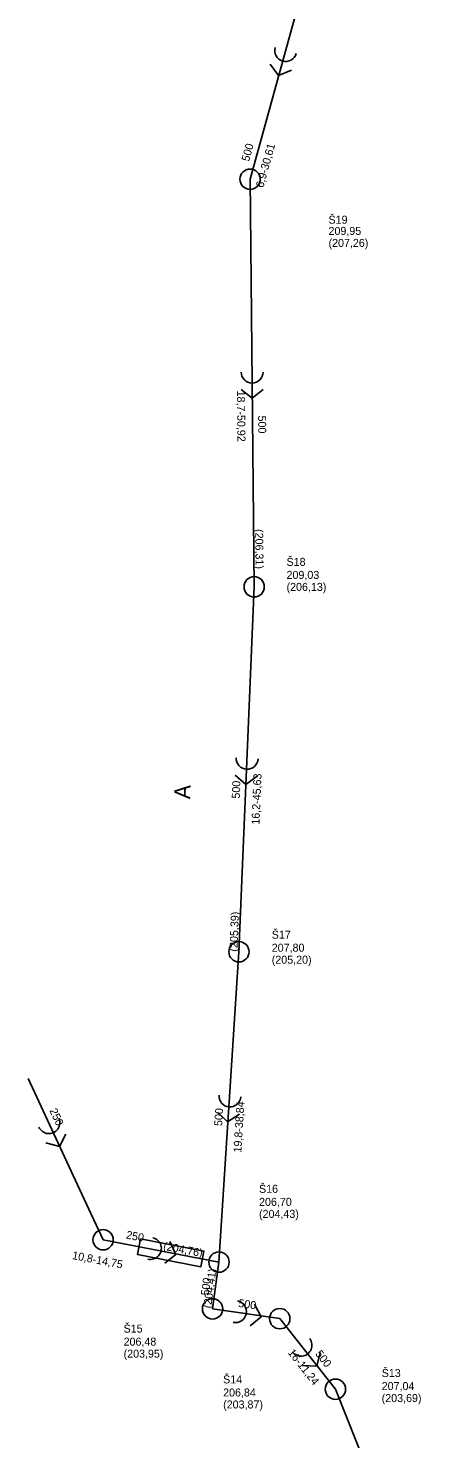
# Model space of a CAD drawing. Extents: x -569540 to -569072, y -1179643 to -1178245.
# Drawn here: x -569540.5 to -569488.5, y -1179470.9 to -1179294.7 of the extents above; entities that cross this region are included whole.
import ezdxf

# ---------------------------------------------------------------- set-up
doc = ezdxf.new("R2010")
doc.units = 0
for name, color, linetype in [('Vrstva 1', 7, 'Continuous'), ('Vrstva 15', 7, 'Continuous'), ('Vrstva 27', 7, 'Continuous'), ('Vrstva 29', 7, 'Continuous'), ('Vrstva 35', 7, 'Continuous'), ('Vrstva 41', 7, 'Continuous'), ('Vrstva 44', 7, 'Continuous'), ('Vrstva 45', 7, 'Continuous'), ('Vrstva 56', 7, 'Continuous'), ('Vrstva 57', 7, 'Continuous')]:
    doc.layers.add(name, color=color, linetype=linetype)

# ---------------------------------------------------------------- blocks, each defined once
blk = doc.blocks.new('100')
at = {"layer": 'Vrstva 1'}
blk.add_circle((0, 0), 1.27, dxfattribs=at)
blk = doc.blocks.new('86')
at = {"layer": 'Vrstva 1'}
blk.add_lwpolyline([(0.79, 1.37), (1.89, 0), (0.79, -1.38)], dxfattribs=at)
blk.add_arc((-1.37, 0), 1.37, 270, 90, dxfattribs=at)

msp = doc.modelspace()

# ---------------------------------------------------------------- linework, layer by layer
at = {"layer": 'Vrstva 15'}
for p, q in [((-569504.59, -1179284.05), (-569512.73, -1179313.56)), ((-569512.73, -1179313.56), (-569512.22, -1179364.48)), ((-569512.22, -1179364.48), (-569514.12, -1179410.07)), ((-569514.12, -1179410.07), (-569516.62, -1179448.83)), ((-569531.11, -1179446.05), (-569516.62, -1179448.83)), ((-569516.62, -1179448.83), (-569517.42, -1179454.68)), ((-569517.42, -1179454.68), (-569509.02, -1179455.9)), ((-569509.02, -1179455.9), (-569502.06, -1179464.71)), ((-569502.06, -1179464.71), (-569488.5, -1179498.74))]:
    msp.add_line(p, q, dxfattribs=at)
msp.add_lwpolyline([(-569540.48, -1179425.88), (-569533.76, -1179440.34), (-569531.11, -1179446.05)], dxfattribs=at)
at = {"layer": 'Vrstva 27'}
msp.add_lwpolyline([(-569526.42, -1179445.93), (-569518.5, -1179447.45), (-569518.88, -1179449.41), (-569526.79, -1179447.9), (-569526.42, -1179445.93)], dxfattribs=at)

# ---------------------------------------------------------------- block references
at = {"layer": 'Vrstva 29'}
for p, xscale, yscale, rotation in [((-569512.73, -1179313.56), 1.000191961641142, 1.000191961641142, 82.91099886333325), ((-569512.22, -1179364.48), 0.9999999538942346, 0.9999999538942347, -92.0000000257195), ((-569514.12, -1179410.07), 0.9999999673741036, 0.9999999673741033, -93.99999995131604), ((-569531.11, -1179446.05), 0.9999999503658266, 0.9999999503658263, 142.00000018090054), ((-569516.62, -1179448.83), 1.000191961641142, 1.000191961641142, -97.08900113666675), ((-569517.42, -1179454.68), 0.9999999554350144, 0.9999999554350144, 126.99999920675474), ((-569509.02, -1179455.9), 0.9999999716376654, 0.9999999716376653, 150.00000103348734), ((-569502.06, -1179464.71), 0.9999999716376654, 0.9999999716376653, 119.99999896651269)]:
    msp.add_blockref('100', p, dxfattribs=dict(at, xscale=xscale, yscale=yscale, rotation=rotation))
at = {"layer": 'Vrstva 41'}
for p, xscale, yscale, rotation in [((-569508.66, -1179298.8), 0.9999999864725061, 0.9999999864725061, -105.99999860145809), ((-569513.17, -1179387.27), 0.9999999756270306, 0.9999999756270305, -93.00000001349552), ((-569515.37, -1179429.45), 0.9999999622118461, 0.999999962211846, -94.99999985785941), ((-569537.33, -1179432.67), 0.9999999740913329, 0.9999999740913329, -65.99999939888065), ((-569523.86, -1179447.44), 1.0045862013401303, 1.00458620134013, -13.17409066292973), ((-569513.22, -1179455.29), 1.00837761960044, 1.00837761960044, -11.626378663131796), ((-569505.54, -1179460.31), 0.9999999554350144, 0.9999999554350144, -53.00000079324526)]:
    msp.add_blockref('86', p, dxfattribs=dict(at, xscale=xscale, yscale=yscale, rotation=rotation))
at = {"layer": 'Vrstva 41', "rotation": -90}
msp.add_blockref('86', (-569512.48, -1179339.02), dxfattribs=at)

# ---------------------------------------------------------------- texts
at = {"layer": 'Vrstva 35'}
msp.add_text('A', height=2, rotation=87.61, dxfattribs=at).set_placement((-569520.23, -1179391.03))
at = {"layer": 'Vrstva 44'}
for s, rotation, p in [('500', 74.57, (-569512.86, -1179311.41)), ('500', 270.57, (-569511.73, -1179343.09)), ('500', 87.61, (-569514.03, -1179390.95)), ('250', 294.92, (-569537.85, -1179429.89)), ('500', 86.32, (-569516.23, -1179431.86)), ('250', 349.15, (-569528.3, -1179445.88)), ('500', 82.25, (-569517.91, -1179453.07)), ('500', 351.7, (-569514.25, -1179454.43)), ('500', 308.34, (-569504.63, -1179460.33))]:
    msp.add_text(s, height=1, rotation=rotation, dxfattribs=at).set_placement(p)
at = {"layer": 'Vrstva 45'}
for s, rotation, p in [('6,9-30,61', 74.57, (-569511.08, -1179314.7)), ('18,7-50,92', 270.57, (-569514.37, -1179339.97)), ('(206,31)', 270.57, (-569512.09, -1179357.27)), ('16,2-45,63', 87.61, (-569511.56, -1179394.21)), ('(205,39)', 87.61, (-569514.32, -1179410.06)), ('19,8-38,84', 86.32, (-569513.83, -1179435.17)), ('(204,76)', 349.15, (-569523.65, -1179447.28)), ('10,8-14,75', 349.15, (-569535.04, -1179448.44)), ('(204,41)', 82.25, (-569517.61, -1179454.65)), ('16-11,24', 308.34, (-569508.06, -1179460.17))]:
    msp.add_text(s, height=1, rotation=rotation, dxfattribs=at).set_placement(p)
at = {"layer": 'Vrstva 56'}
for s, p in [('209,95 ', (-569502.92, -1179320.52)), ('(207,26)', (-569502.92, -1179322.02)), ('209,03 ', (-569508.17, -1179363.49)), ('(206,13)', (-569508.17, -1179364.99)), ('207,80 ', (-569510.02, -1179410.06)), ('(205,20)', (-569510.02, -1179411.56)), ('206,70 ', (-569511.61, -1179441.81)), ('(204,43)', (-569511.61, -1179443.31)), ('206,48 ', (-569528.55, -1179459.27)), ('(203,95)', (-569528.55, -1179460.77)), ('207,04 ', (-569496.27, -1179464.82)), ('206,84 ', (-569516.1, -1179465.62)), ('(203,69)', (-569496.27, -1179466.32)), ('(203,87)', (-569516.1, -1179467.12))]:
    msp.add_text(s, height=1, dxfattribs=at).set_placement(p)
at = {"layer": 'Vrstva 57'}
for s, p in [('Š19', (-569502.92, -1179319.12)), ('Š18', (-569508.17, -1179361.86)), ('Š17', (-569510.02, -1179408.43)), ('Š16', (-569511.61, -1179440.18)), ('Š15', (-569528.55, -1179457.64)), ('Š13', (-569496.27, -1179463.19)), ('Š14', (-569516.1, -1179463.99))]:
    msp.add_text(s, height=1, dxfattribs=at).set_placement(p)

doc.saveas('drawing.dxf')
